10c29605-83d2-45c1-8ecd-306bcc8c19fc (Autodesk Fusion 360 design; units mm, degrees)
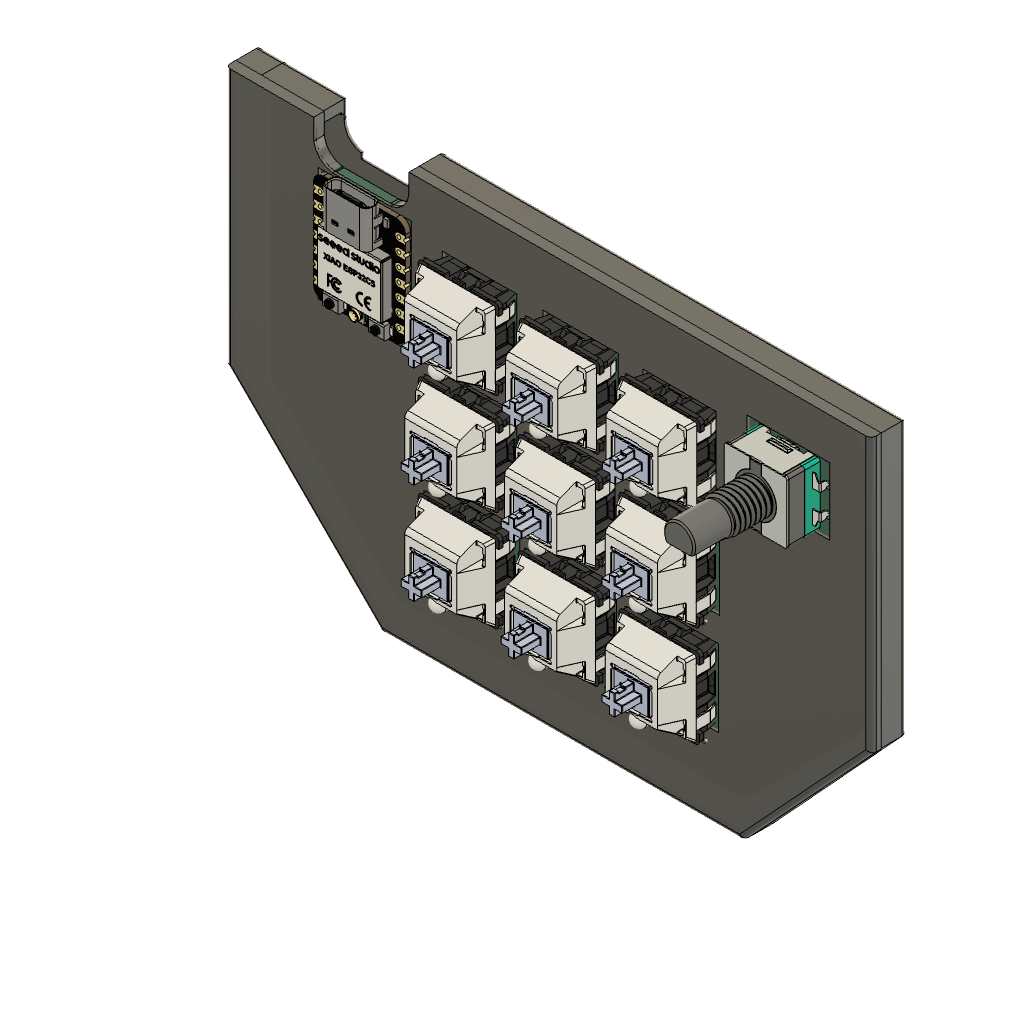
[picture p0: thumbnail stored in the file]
part number: 2026-09-27-00-28-18-834
part number: 2026-09-27-00-29-39-805
part number: 2026-09-27-00-34-33-022
component_insert "Component Insert"
sketch "Sketch1" plane through (0, 0, 0) normal (0, 0, 1) x axis (1, 0, 0)
  line L1 (225, -55) -> (105, -55)
  line L2 (225, -107.8447) -> (225, -55)
  line L3 (200, -135) -> (225, -107.8447)
  line L4 (130, -135) -> (200, -135)
  line L5 (100, -105) -> (130, -135)
  line L6 (100, -55) -> (100, -105)
  line L7 (105, -55) -> (100, -55)
  horizontal L1
  perpendicular L1 L2
  perpendicular L2 L4
  perpendicular L1 L6
extrude "Extrude1" new body sketch "Sketch1" against normal blind 5
extrude "Extrude2" cut of existing geometry blind -5
sketch "Sketch2" plane through (0, 0, 0) normal (0, 0, 1) x axis (1, 0, 0)
  line L1 (100, -105) -> (100, -55)
  line L2 (130, -135) -> (100, -105)
  line L3 (200, -135) -> (130, -135)
  line L4 (225, -107.8447) -> (200, -135)
  line L5 (225, -55) -> (225, -107.8447)
  line L6 (105, -55) -> (225, -55)
  line L7 (100, -55) -> (105, -55)
  line L8 (117, -58.5) -> (117, -57)
  line L9 (131.5, -62.5) -> (121, -62.5)
  line L10 (135.5, -57) -> (135.5, -58.5)
  line L11 (218, -57) -> (135.5, -57)
  line L12 (222, -104.8431) -> (222, -61)
  line L13 (199.6716, -128.8284) -> (220.8284, -107.6716)
  line L14 (133.1569, -130) -> (196.8431, -130)
  line L15 (107.6716, -106.1716) -> (130.3284, -128.8284)
  line L16 (106.5, -58) -> (106.5, -103.3431)
  line L17 (107.5, -57) -> (106.5, -58)
  line L18 (117, -57) -> (107.5, -57)
  line L19 (130, -130) -> (200, -130)
  line L20 (106.8045, -104.8739) -> (130, -130)
  line L21 (106.5, -57.5) -> (106.8045, -104.8739)
  line L22 (222.3802, -56.7552) -> (106.5, -57.5)
  line L23 (222.6991, -106.3739) -> (222.3802, -56.7552)
  line L24 (200, -130) -> (222.6991, -106.3739)
  arc A1 centre (121, -58.5) radius 4 clockwise from (121, -62.5) to (117, -58.5)
  arc A2 centre (131.5, -58.5) radius 4 clockwise from (135.5, -58.5) to (131.5, -62.5)
  arc A3 centre (218, -61) radius 4 clockwise from (218, -57) to (222, -61)
  arc A4 centre (218, -104.8431) radius 4 clockwise from (222, -104.8431) to (220.8284, -107.6716)
  arc A5 centre (196.8431, -126) radius 4 clockwise from (199.6716, -128.8284) to (196.8431, -130)
  arc A6 centre (133.1569, -126) radius 4 clockwise from (133.1569, -130) to (130.3284, -128.8284)
  arc A7 centre (110.5, -103.3431) radius 4 clockwise from (107.6716, -106.1716) to (106.5, -103.3431)
  point P36 (106.8045, -104.8739)
  parallel L14 L19
  midpoint A7 P36
  perpendicular L21 L22
  perpendicular L22 L23
extrude "Extrude3" cut sketch "Sketch2" profile of L8 A1 L9 A2 L10 L11 A3 L12 A4 L13 A5 L14 A6 L15 L17 L19 L20 L21 L22 against normal blind 4
sketch "Sketch3" plane through (0, 0, 0) normal (0, 0, 1) x axis (1, 0, 0)
  line L1 (100, -105) -> (100, -55)
  line L2 (130, -135) -> (100, -105)
  line L3 (200, -135) -> (130, -135)
  line L4 (225, -107.8447) -> (200, -135)
  line L5 (225, -55) -> (225, -107.8447)
  line L6 (105, -55) -> (225, -55)
  line L7 (100, -55) -> (105, -55)
  line L8 (117, -58.5) -> (117, -57)
  line L9 (131.5, -62.5) -> (121, -62.5)
  line L10 (135.5, -57) -> (135.5, -58.5)
  line L11 (218, -57) -> (135.5, -57)
  line L12 (222, -104.8431) -> (222, -61)
  line L13 (199.6716, -128.8284) -> (220.8284, -107.6716)
  line L14 (133.1569, -130) -> (196.8431, -130)
  line L15 (107.6716, -106.1716) -> (130.3284, -128.8284)
  line L16 (106.5, -58) -> (106.5, -103.3431)
  line L17 (107.5, -57) -> (106.5, -58)
  line L18 (117, -57) -> (107.5, -57)
  line L19 (135.5, -55) -> (117, -55)
  line L20 (135.5, -58.8508) -> (135.5, -55)
  line L21 (117, -58.8508) -> (135.5, -58.8508)
  line L22 (117, -55) -> (117, -58.8508)
  line L23 (120.3313, -62.4437) -> (131.5, -62.5)
  arc A1 centre (121, -58.5) radius 4 clockwise from (121, -62.5) to (117, -58.5)
  arc A2 centre (131.5, -58.5) radius 4 clockwise from (135.5, -58.5) to (131.5, -62.5)
  arc A3 centre (218, -61) radius 4 clockwise from (218, -57) to (222, -61)
  arc A4 centre (218, -104.8431) radius 4 clockwise from (222, -104.8431) to (220.8284, -107.6716)
  arc A5 centre (196.8431, -126) radius 4 clockwise from (199.6716, -128.8284) to (196.8431, -130)
  arc A6 centre (133.1569, -126) radius 4 clockwise from (133.1569, -130) to (130.3284, -128.8284)
  arc A7 centre (110.5, -103.3431) radius 4 clockwise from (107.6716, -106.1716) to (106.5, -103.3431)
  arc A8 centre (131.5, -58.4831) radius 4.0169 clockwise from (135.5, -58.8508) to (131.5, -62.5)
  arc A9 centre (121.0034, -58.4797) radius 4.0206 clockwise from (120.3313, -62.4437) to (117, -58.8508)
  point P34 (117, -55)
  point P13 (131.5, -62.5)
  point P38 (131.5, -62.5)
  point P40 (120.3313, -62.4437)
  point P42 (131.5, -62.5)
  horizontal L19
  vertical L20
  horizontal L21
  vertical L22
  coincident L6 P34
  tangent A2 A8
  coincident P13 P38
  tangent A1 A9
  coincident A1 P40
  coincident P13 P42
extrude "Extrude4" cut sketch "Sketch3" profile of L6 L8 A1 A2 L10 L19 L20 L21 L22 L23 against normal blind 11
extrude "Extrude5" cut of existing geometry blind -1
sketch "Sketch4" plane through (0, 0, 0) normal (0, 0, 1) x axis (1, 0, 0)
  line L1 (135.5, -57) -> (135.5, -55)
  line L2 (218, -57) -> (135.5, -57)
  line L3 (222, -104.8431) -> (222, -61)
  line L4 (199.6716, -128.8284) -> (220.8284, -107.6716)
  line L5 (133.1569, -130) -> (196.8431, -130)
  line L6 (107.6716, -106.1716) -> (130.3284, -128.8284)
  line L7 (106.5, -58) -> (106.5, -103.3431)
  line L8 (107.5, -57) -> (106.5, -58)
  line L9 (117, -57) -> (107.5, -57)
  line L10 (117, -55) -> (117, -57)
  line L11 (105, -55) -> (117, -55)
  line L12 (100, -55) -> (105, -55)
  line L13 (100, -105) -> (100, -55)
  line L14 (130, -135) -> (100, -105)
  line L15 (200, -135) -> (130, -135)
  line L16 (225, -107.8447) -> (200, -135)
  line L17 (225, -55) -> (225, -107.8447)
  line L18 (135.5, -55) -> (225, -55)
  arc A1 centre (218, -61) radius 4 clockwise from (218, -57) to (222, -61)
  arc A2 centre (218, -104.8431) radius 4 clockwise from (222, -104.8431) to (220.8284, -107.6716)
  arc A3 centre (196.8431, -126) radius 4 clockwise from (199.6716, -128.8284) to (196.8431, -130)
  arc A4 centre (133.1569, -126) radius 4 clockwise from (133.1569, -130) to (130.3284, -128.8284)
  arc A5 centre (110.5, -103.3431) radius 4 clockwise from (107.6716, -106.1716) to (106.5, -103.3431)
sketch "Sketch5" plane through (0, 0, 0) normal (0, 0, 1) x axis (1, 0, 0)
  line L1 (130, -135) -> (200, -135)
  line L2 (100, -105) -> (130, -135)
  line L3 (100, -55) -> (100, -105)
  line L4 (117.1258, -55) -> (100, -55)
  line L5 (117.1258, -59) -> (117.1258, -55)
  line L6 (135.5114, -55) -> (135.5114, -58.9321)
  line L7 (225, -55) -> (135.5114, -55)
  line L8 (225, -108) -> (225, -55)
  line L9 (200, -135) -> (225, -108)
  line L10 (120.7213, -62.5112) -> (132, -62.5)
  arc A1 centre (131.399, -58.3966) radius 4.1472 clockwise from (135.5114, -58.9321) to (132, -62.5)
  arc A2 centre (121.2244, -58.3994) radius 4.1424 clockwise from (120.7213, -62.5112) to (117.1258, -59)
  horizontal L1
  perpendicular L1 L3
  perpendicular L3 L4
  perpendicular L1 L5
  vertical L6
  perpendicular L6 L7
  perpendicular L7 L8
extrude "Extrude1" new body sketch "Sketch5" along normal blind 2
sketch "Sketch6" plane through (0, 0, 2) normal (0, 0, 1) x axis (1, 0, 0)
  line L1 (120.7213, -62.5112) -> (132, -62.5)
  line L2 (117.1258, -55) -> (117.1258, -59)
  line L3 (100, -55) -> (117.1258, -55)
  line L4 (100, -105) -> (100, -55)
  line L5 (130, -135) -> (100, -105)
  line L6 (200, -135) -> (130, -135)
  line L7 (225, -108) -> (200, -135)
  line L8 (225, -55) -> (225, -108)
  line L9 (135.5114, -55) -> (225, -55)
  line L10 (135.5114, -58.9321) -> (135.5114, -55)
  line L11 (136, -63) -> (118, -63)
  line L12 (136, -85) -> (136, -63)
  line L13 (118, -85) -> (136, -85)
  line L14 (118, -63) -> (118, -85)
  line L15 (156.4385, -65) -> (142, -65)
  line L16 (156.4385, -79.6903) -> (156.4385, -65)
  line L17 (142, -79.6903) -> (156.4385, -79.6903)
  line L18 (142, -65) -> (142, -79.6903)
  line L19 (156.4385, -85) -> (142, -85)
  line L20 (156.4385, -99.2533) -> (156.4385, -85)
  line L21 (142, -99.2533) -> (156.4385, -99.2533)
  line L22 (142, -85) -> (142, -99.2533)
  line L23 (176.0657, -65.1524) -> (161.4836, -65.1524)
  line L24 (176.0657, -79.6903) -> (176.0657, -65.1524)
  line L25 (161.4836, -79.6903) -> (176.0657, -79.6903)
  line L26 (161.4836, -65.1524) -> (161.4836, -79.6903)
  line L27 (156.4385, -85) -> (142, -85)
  line L28 (156.4385, -99.2533) -> (156.4385, -85)
  line L29 (142, -99.2533) -> (156.4385, -99.2533)
  line L30 (142, -85) -> (142, -99.2533)
  line L31 (175.4581, -85) -> (161.2558, -85)
  line L32 (175.4581, -99.2533) -> (175.4581, -85)
  line L33 (161.2558, -99.2533) -> (175.4581, -99.2533)
  line L34 (161.2558, -85) -> (161.2558, -99.2533)
  line L35 (195, -65.3832) -> (180.8474, -65.3832)
  line L36 (195, -80) -> (195, -65.3832)
  line L37 (180.8474, -80) -> (195, -80)
  line L38 (180.8474, -65.3832) -> (180.8474, -80)
  line L39 (217, -63) -> (201, -63)
  line L40 (217, -76) -> (217, -63)
  line L41 (201, -76) -> (217, -76)
  line L42 (201, -63) -> (201, -76)
  line L43 (195.6574, -84.6741) -> (180.6955, -84.6741)
  line L44 (195.6574, -99.2533) -> (195.6574, -84.6741)
  line L45 (180.6955, -99.2533) -> (195.6574, -99.2533)
  line L46 (180.6955, -84.6741) -> (180.6955, -99.2533)
  line L47 (157, -104.1109) -> (141.6101, -104.1109)
  line L48 (157, -119) -> (157, -104.1109)
  line L49 (141.6101, -119) -> (157, -119)
  line L50 (141.6101, -104.1109) -> (141.6101, -119)
  line L51 (175.711, -104.1109) -> (160.977, -104.1109)
  line L52 (175.711, -119) -> (175.711, -104.1109)
  line L53 (160.977, -119) -> (175.711, -119)
  line L54 (160.977, -104.1109) -> (160.977, -119)
  line L55 (195.4576, -104.1109) -> (180.6477, -104.1109)
  line L56 (195.4576, -119) -> (195.4576, -104.1109)
  line L57 (180.6477, -119) -> (195.4576, -119)
  line L58 (180.6477, -104.1109) -> (180.6477, -119)
  line L59 (176.0608, -85) -> (161.2558, -85)
  line L60 (176.0608, -99.2533) -> (176.0608, -85)
  line L61 (161.2558, -99.2533) -> (176.0608, -99.2533)
  line L62 (161.2558, -85) -> (161.2558, -99.2533)
  arc A1 centre (131.399, -58.3966) radius 4.1472 clockwise from (135.5114, -58.9321) to (132, -62.5)
  arc A2 centre (121.2244, -58.3994) radius 4.1424 clockwise from (120.7213, -62.5112) to (117.1258, -59)
  horizontal L11
  vertical L12
  horizontal L13
  vertical L14
  horizontal L15
  vertical L16
  horizontal L17
  vertical L18
  horizontal L19
  vertical L20
  horizontal L21
  vertical L22
  horizontal L23
  vertical L24
  horizontal L25
  vertical L26
  horizontal L27
  vertical L28
  horizontal L29
  vertical L30
  horizontal L31
  vertical L32
  horizontal L33
  vertical L34
  horizontal L35
  vertical L36
  horizontal L37
  vertical L38
  horizontal L39
  vertical L40
  horizontal L41
  vertical L42
  horizontal L43
  vertical L44
  horizontal L45
  vertical L46
  horizontal L47
  vertical L48
  horizontal L49
  vertical L50
  horizontal L51
  vertical L52
  horizontal L53
  vertical L54
  horizontal L55
  vertical L56
  horizontal L57
  vertical L58
  horizontal L59
  vertical L60
  horizontal L61
  vertical L62
extrude "Extrude2" cut sketch "Sketch6" profile of L11 L12 L13 L14 L15 L16 L17 L18 L19 L20 L21 L22 L23 L24 L25 L26 L27 L28 L29 L30 L31 L32 L33 L34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 against normal blind 2
fillet "Fillet1" radius 1
fillet "Fillet1" radius 1
fillet "Fillet2" radius 1
fillet "Fillet3" radius 1
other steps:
create_component "CreateComponent1"
create_component "CreateComponent2"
